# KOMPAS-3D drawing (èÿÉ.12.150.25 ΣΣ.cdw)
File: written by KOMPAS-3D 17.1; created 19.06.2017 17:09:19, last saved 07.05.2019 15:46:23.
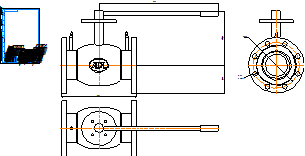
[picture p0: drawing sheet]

Sheet 1: A4, portrait

Title block, sheet 1: name: КШР.12.150.25 фф; material: Внимание! Данный продукт является объектом авторского права ООО «Торговый Дом АДЛ». / Запрещается изменение, копирование, распространение / (в том числе путем копирования на другие сайты и ресурсы в Интернете) / или любое иное использование информации и объектов без предварительного / согласия правообладателя (ООО «Торговый Дом АДЛ»).; scale: 1:1; sheets: 1; organisation: ООО "Торговый дом АДЛ"; sheet format: A4; stored path: C:\Users\tra\Desktop\2д чертежи\Шаровые краны БИВАЛ\КШР_Бивал_серия_12\KOMPAS 2D\КШР.12.150.25 фф.cdw

Views: Спереди 1, Проекционный вид 2, Проекционный вид 3
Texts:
  Klimkovich
  ADL
Dimensions and other numbers on the sheet: 407; 645; 291,6; 150; 250; 26; 8 Отв.; 1:1; 1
